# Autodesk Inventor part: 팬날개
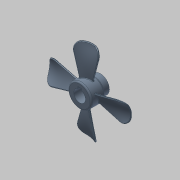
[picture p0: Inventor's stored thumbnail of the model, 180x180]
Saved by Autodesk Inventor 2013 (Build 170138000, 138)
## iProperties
Company: 한국ATC센터
Created: 2016-06
Part Number: 팬날개
Document SubType Name: Modeling
Designer: mdu
Density: 1.06 g/cm^3
Material: ABS 플라스틱
Mass: 26.2509 g
Surface Area: 149.775 cm^2
Volume: 24.765 cm^3
Author: mdu
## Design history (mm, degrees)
sketch "스케치1"
  geometry: L1 (-15, 0)-(15, 0); L2 (-15, 0)-(-15, 17); L3 (-15, 17)-(5, 17); L4 (5, 17)-(5, 13); L5 (5, 13)-(15, 13); L6 (15, 13)-(15, 0); 2 further points
  constraints: 12 end point, 3 parallel, 2 perpendicular, 1 coincident, 1 horizontal, 1 midpoint
  dimensions: "d0" = 30 distance of L1.start L1.end; "d8" = 34 diameter of L3 L1; "d10" = 26 diameter of L5 L1; "d32" = 20 distance of L2.end L3.end
revolve "회전1" sketch "스케치1" stored, may be unused: angle "d11" = 90 deg
node "작업 평면2"
sketch "스케치7"
  geometry: L1 (-15, 17)-(5, 17) reference; L2 (-15, -17)-(5, -17) reference; L3 (-5, 17)-(-5, -17); A1 r 35 centre (-36.399, -13.457) between (-2, -7) and (-8, 7); 1 further point
  constraints: 2 end point, 2 midpoint, 2 point on circle, 1 centre point
  dimensions: "d36" = 35 radius of A1; "d37" = 10 distance from line of A1.start L2; "d38" = 10 distance from line of A1.end L1; "d45" = 3 distance from line of A1.end L3; "d46" = 3 distance from line of A1.start L3
sketch "3D 스케치1"
  geometry: L1 through (0, 0) direction (1, 0) reference; L2 through (0, 0) direction (1, 0) reference; 13 other entities
  constraints: 2 collinear
  node "투영 원본 위치 스케치7"
sketch "스케치8"
  geometry: L1 (-15, 17)-(5, 17) reference; L2 (-15, -17)-(5, -17) reference; L3 (-5, 17)-(-5, -17); A1 r 30 centre (-28.74, -3.591) between (-3, -19) and (-9, 19); 1 further point
  constraints: 2 end point, 2 midpoint, 2 point on circle, 1 centre point
  dimensions: "d43" = 30 radius of A1; "d47" = 4 distance from line of A1.end L3; "d48" = 2 distance from line of A1.start L3; "d58" = 2 distance from line of A1.end L1; "d59" = 2 distance from line of A1.start L2
sketch "3D 스케치2"
sketch "3D 스케치3"
feature "경계 패치1" sketch "3D 스케치2", "3D 스케치3" dims "d50" = 0
feature "연장1" dims "d55" = 2
feature "두껍게 하기1" dims "d51" = 2, "d52" = 2
sketch "스케치9"
  geometry: C1 r 59 at (0, 0); 1 further point
  constraints: 1 centre point, 1 coincident
  dimensions: "d60" = 118 diameter of C1
extrude "돌출2" sketch "스케치9" distance "d62" = 200; taper "d63" = 0 deg
fillet "모깎기6" dims "d64" = 10
fillet "모깎기7" dims "d66" = 0.8
fillet "모깎기8" dims "d67" = 0.8
sketch "스케치2"
  geometry: L1 (-2.5, 8.124)-(-2.5, 10.8); L2 (-2.5, 10.8)-(2.5, 10.8); L3 (2.5, 10.8)-(2.5, 8.124); A1 r 8.5 centre (0, 0) between (-2.5, 8.124) and (2.5, 8.124); 1 further point
  constraints: 6 end point, 2 parallel, 2 point on circle, 1 centre point, 1 coincident, 1 horizontal, 1 vertical
  dimensions: "d12" = 17 diameter of A1; "d13" = 5 distance of L1.end L2.end; "d14" = 19.3 dimension on A1 L2 (computed from d12)
extrude "돌출1" cut sketch "스케치2" stored distance "d15" = 10; taper "d16" = 0 deg
chamfer "모따기1" distance "d17" = 1; stored, may be unused: second distance "d18" = 2, angle "d19" = 45 deg
node "작업 평면1"
sketch "스케치3"
  geometry: L1 (5, -13)-(5, 13) reference; 3 further points
  constraints: 1 horizontal alignment, 1 midpoint
  dimensions: "d20" = 5 distance from line of L1 point (0, 0)
hole "구멍1" sketch "스케치3" at (0, 0) diameter "d21" = 3.242; stored, may be unused: countersink angle "d25" = 90 deg, drill point angle "d27" = 118 deg; dims "d22" = 6, "d23" = 4, "d24" = 2, "d26" = 8
fillet "모깎기9" dims "d77" = 2
fillet "모깎기10" dims "d78" = 2
fillet "모깎기11" dims "d79" = 2
node "솔리드1"
pattern_circular "원형 패턴1" dims "d69" = 360 deg
pattern_circular "원형 패턴2" dims angle "d72" = 360 deg
pattern_circular "원형 패턴3" dims angle "d75" = 360 deg
node "투영 원본 위치 스케치8"
node "곡면1"
node "곡면2"
node "곡면3"
node "곡면4"
feature "경계 패치2"
feature "경계 패치3"
feature "경계 패치4"
